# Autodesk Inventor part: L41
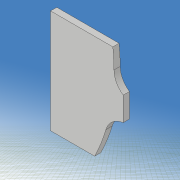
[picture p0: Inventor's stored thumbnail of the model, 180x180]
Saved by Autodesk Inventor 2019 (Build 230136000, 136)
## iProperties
Created: 2021-05
Part Number: L41
Material: 一般
Document SubType Name: Modeling
Designer: kikut
Density: 1 g/cm^3
Appearance: 既定
Mass: 0.00934248 g
Surface Area: 0.426451 cm^2
Volume: 0.00934248 cm^3
Author: kikut
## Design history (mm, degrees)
sketch "スケッチ1"
  geometry: L1 (80, 60)-(-80, 60); L2 (-80, 60)-(-80, -60); L3 (-80, -60)-(80, -60); L4 (80, -60)-(80, 60); L5 (80, 60)-(-80, -60); L6 (-80, 60)-(80, -60); 1 further point
  constraints: 12 end point, 2 midpoint, 2 parallel, 1 horizontal, 1 perpendicular
  dimensions: "d0" = 160 distance of L2.end L3.end; "d1" = 120 distance of L1.end L2.end
extrude "押し出し1" new body sketch "スケッチ1" stored distance "d2" = 0.6; taper "d3" = 0 deg
sketch "スケッチ2"
  geometry: L1 (-140, 0)-(140, 0) reference; L2 (0, -54)-(20, -30); L3 (0, 54)-(20, 30); L4 (0, -3)-(6.514, -3); L5 (6.514, -3)-(16, -6); L6 (16, -6)-(24, -3); L7 (24, -3)-(33.716, -3); L8 (0, 3)-(6.514, 3); L9 (6.514, 3)-(16, 6); L10 (16, 6)-(24, 3); L11 (24, 3)-(33.716, 3); L12 (0, -98)-(0, 98) reference; L13 (-100, -70)-(100, -70); L14 (100, -70)-(100, 70); L15 (100, 70)-(-100, 70); L16 (-100, 70)-(-100, -70); L17 (-100, -70)-(100, 70); L18 (100, -70)-(-100, 70); A1 r 60 centre (54.312, 28.5) between (0, 54) and (0, 3); A2 r 60 centre (54.312, -28.5) between (0, -3) and (0, -54); A3 r 18.111 centre (18, -12) between (20, -30) and (33.716, -3); A4 r 18.111 centre (18, 12) between (33.716, 3) and (20, 30); 1 further point
  constraints: 32 end point, 8 point on circle, 8 symmetric about line, 4 centre point, 3 horizontal, 2 collinear, 2 midpoint, 2 parallel, 1 perpendicular
  dimensions: "d5" = 60 radius of A1; "d6" = 6 distance of L8.start L4.start; "d7" = 108 distance of L3.start L2.start; "d8" = 0 horizontal distance of L3.start L8.start; "d9" = 60 distance of L3.end L2.end; "d10" = 0 horizontal distance of point (0, 0) L3.start; "d11" = 20 horizontal distance of L3.start L3.end; "d12" = 24 distance of A4.centre A3.centre; "d13" = 6 distance of L11.end L7.end; "d14" = 12 distance of L9.end L5.end; "d15" = 16 distance from line of L12 L5.end; "d16" = 24 distance from line of L6.end L12; "d17" = 200 distance of L14.end L15.end; "d18" = 140 distance of L15.end L13.start; "d30" = 18 distance from line of L12 A4.centre
extrude "押し出し2" cut sketch "スケッチ2" stored distance "d19" = 10; taper "d20" = 0 deg
sketch "スケッチ3"
  geometry: L1 (49.705, -17.97)-(33.948, -15.191); L2 (33.948, -15.191)-(34.295, -13.222); L3 (34.295, -13.222)-(50.052, -16); L4 (50.052, -16)-(49.705, -17.97); L5 (49.705, -17.97)-(34.295, -13.222); L6 (33.948, -15.191)-(50.052, -16); L7 (50.052, 16)-(34.295, 13.222); L8 (34.295, 13.222)-(33.948, 15.191); L9 (33.948, 15.191)-(49.705, 17.97); L10 (49.705, 17.97)-(50.052, 16); L11 (50.052, 16)-(33.948, 15.191); L12 (34.295, 13.222)-(49.705, 17.97); L13 (-112, 0)-(112, 0) reference; L14 (0, -84)-(0, 84) reference; 3 further points
  constraints: 24 end point, 4 midpoint, 4 parallel, 2 perpendicular, 2 symmetric about line
  dimensions: "d21" = 2 distance of L3.end L1.start; "d22" = 2 distance of L9.end L7.start; "d23" = 16 distance of L8.end L9.end; "d24" = 42 distance from line of L14 point (42, 15.596); "d26" = 10 deg angle of L7 L13; "d62" = 16 distance from line of L3.end L13
extrude "押し出し3" join sketch "スケッチ3" distance "d27" = 0.6; taper "d28" = 0 deg
fillet "フィレット1" dims "d31" = 2
fillet "フィレット2" dims "d32" = 1
sketch "スケッチ7"
  geometry: L1 (-20, 60)-(80, 60); L2 (80, 60)-(80, -60); L3 (80, -60)-(-20, -60); L4 (-20, -60)-(-20, 60); L5 (0, -82.207)-(0, 85.793) reference; L6 (-40, 0)-(100, 0) reference; L7 (30, -10)-(37, -10); L8 (37, -10)-(37, -20); L9 (37, -20)-(30, -20); L10 (30, -20)-(30, -10); 1 further point
  constraints: 16 end point, 4 parallel, 2 horizontal, 2 perpendicular, 1 other
  dimensions: "d80" = 120 distance of L3.end L1.start; "d81" = 20 distance between parallel lines of L5 L4; "d82" = 100 distance of L1.start L1.end; "d84" = 7 distance of L8.end L9.end; "d85" = 10 distance of L7.end L8.end; "d86" = 50 distance between parallel lines of L4 L10; "d93" = 40 distance between parallel lines of L3 L9
extrude "押し出し5" cut sketch "スケッチ7" stored distance "d87" = 10; taper "d88" = 0 deg
node "ソリッド1"
